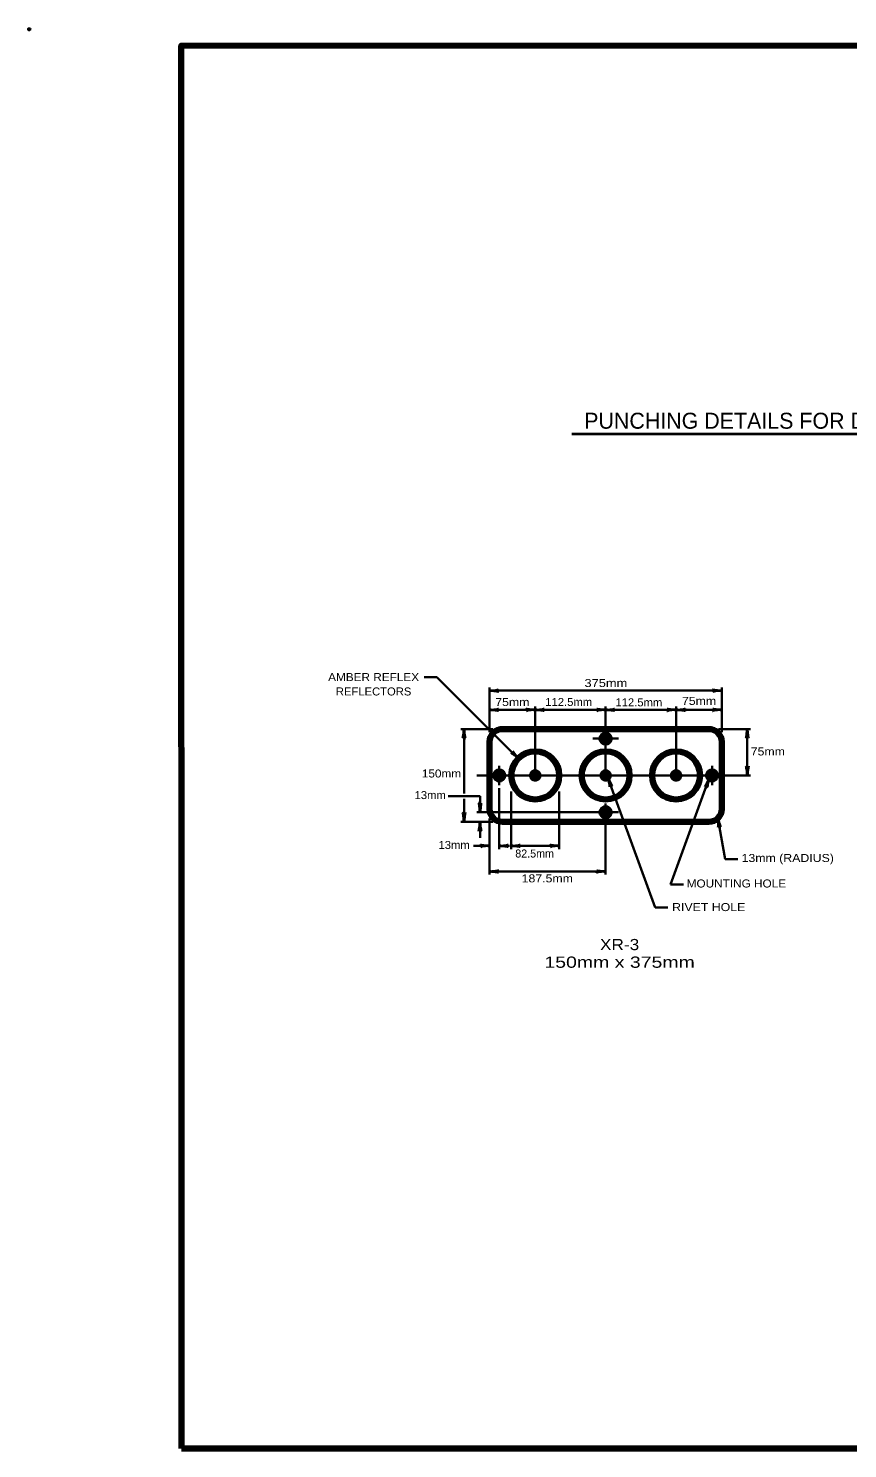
# Model space of a CAD drawing. Extents: x -74 to 639, y -412 to 42.
# Drawn here: x -74.5 to 181.5, y -402.1 to 41.7 of the extents above; entities that cross this region are included whole.
import ezdxf
from ezdxf.enums import TextEntityAlignment as Align

# ---------------------------------------------------------------- set-up
doc = ezdxf.new("R2010")
doc.units = 0
doc.header["$PDMODE"] = 32
doc.header["$PDSIZE"] = 0.5
doc.layers.add('1', color=7, linetype='Continuous', lineweight=40)

msp = doc.modelspace()

# ---------------------------------------------------------------- linework, layer by layer
at = {"layer": '1'}
msp.add_line((95.322, -84.95), (302.217, -84.95), dxfattribs=at)
at = {"layer": '1', "lineweight": 35}
for p, q in [((53.122, -160.979), (49.122, -160.979)), ((78.578, -186.434), (53.122, -160.979)), ((69.631, -178.238), (69.631, -164.238)), ((69.631, -165.238), (142.131, -165.238)), ((142.131, -178.238), (142.131, -164.238)), ((83.881, -171.238), (69.631, -171.238)), ((83.881, -191.738), (83.881, -170.238)), ((105.881, -191.738), (105.881, -170.238)), ((127.881, -191.738), (127.881, -170.238)), ((70.631, -177.238), (60.631, -177.238)), ((61.631, -197.404), (61.631, -177.238)), ((141.131, -177.238), (151.131, -177.238)), ((150.131, -191.738), (150.131, -177.238)), ((105.881, -180.238), (101.881, -180.238)), ((105.881, -180.238), (109.881, -180.238)), ((72.631, -191.738), (72.631, -188.738)), ((139.131, -191.738), (139.131, -188.738)), ((65.631, -191.738), (142.131, -191.738)), ((72.631, -191.738), (72.631, -194.738)), ((106.588, -192.445), (121.334, -232.957)), ((138.247, -192.622), (126.155, -225.845)), ((139.131, -191.738), (139.131, -194.738)), ((142.131, -191.738), (151.131, -191.738)), ((66.631, -198.238), (56.631, -198.238)), ((61.631, -206.238), (61.631, -199.071)), ((66.631, -198.238), (66.631, -203.238)), ((72.631, -195.738), (72.631, -214.738)), ((76.381, -196.738), (76.381, -214.738)), ((91.381, -196.738), (91.381, -214.738)), ((105.881, -203.238), (65.631, -203.238)), ((105.881, -222.738), (105.881, -200.488)), ((105.881, -203.238), (109.881, -203.238)), ((70.631, -206.238), (60.631, -206.238)), ((66.631, -206.238), (66.631, -211.238)), ((69.631, -222.738), (69.631, -205.238)), ((140.959, -205.066), (143.217, -217.869)), ((69.631, -213.738), (64.631, -213.738)), ((75.881, -213.738), (72.631, -213.738)), ((76.381, -213.738), (91.381, -213.738)), ((69.631, -221.738), (105.881, -221.738)), ((143.217, -217.869), (147.217, -217.869)), ((126.155, -225.845), (130.155, -225.845)), ((121.334, -232.957), (125.334, -232.957))]:
    msp.add_line(p, q, dxfattribs=at)
at = {"layer": '1', "lineweight": 90}
for p, q in [((73.631, -177.238), (138.131, -177.238)), ((69.631, -202.238), (69.631, -181.238)), ((142.131, -181.238), (142.131, -202.238)), ((138.131, -206.238), (73.631, -206.238))]:
    msp.add_line(p, q, dxfattribs=at)
at = {"layer": '1', "lineweight": 158}
msp.add_line((633.015, -402.068), (-26.651, -402.068), dxfattribs=at)
msp.add_lwpolyline([(633.015, 36.349), (-26.735, 36.265), (-26.651, -402.068)], dxfattribs=at)
at = {"layer": '1', "lineweight": 35}
msp.add_lwpolyline([(83.881, -171.238), (105.881, -171.238), (127.881, -171.238), (142.131, -171.238)], dxfattribs=at)
at = {"layer": '1', "lineweight": 90}
for centre, radius in [((105.881, -180.238), 1.25), ((83.881, -191.738), 7.5), ((105.881, -191.738), 7.5), ((127.881, -191.738), 7.5), ((72.631, -191.738), 1.25), ((83.881, -191.738), 1), ((105.881, -191.738), 1), ((127.881, -191.738), 1), ((139.131, -191.738), 1.25), ((105.881, -203.238), 1.25)]:
    msp.add_circle(centre, radius, dxfattribs=at)
for centre, start, end in [((73.631, -181.238), 90, 180), ((138.131, -181.238), 0, 90), ((73.631, -202.238), 180, 270), ((138.131, -202.238), 270, 0)]:
    msp.add_arc(centre, 4, start, end, dxfattribs=at)
at = {"layer": '1'}
for centre, major_axis, ratio, start_param, end_param in [((70.722, -164.961), (-1.786, -0.156), 0.122415, 0.8963533, 3.1415927), ((70.722, -164.961), (-1.786, -0.156), 0.122415, 0.8963533, 3.1415927), ((70.752, -165.449), (-1.756, 0.176), 0.07063, 3.1407148, 5.41811), ((70.752, -165.449), (-1.756, 0.176), 0.07063, 3.1407148, 5.41811), ((141.04, -165.514), (1.786, 0.156), 0.122415, 0.8963533, 3.1415927), ((141.04, -165.514), (1.786, 0.156), 0.122415, 0.8963533, 3.1415927), ((141.01, -165.026), (1.756, -0.176), 0.07063, 3.1407148, 5.41811), ((141.01, -165.026), (1.756, -0.176), 0.07063, 3.1407148, 5.41811), ((70.722, -170.961), (-1.786, -0.156), 0.122415, 0.8963533, 3.1415927), ((70.722, -170.961), (-1.786, -0.156), 0.122415, 0.8963533, 3.1415927), ((70.752, -171.449), (-1.756, 0.176), 0.07063, 3.1407148, 5.41811), ((70.752, -171.449), (-1.756, 0.176), 0.07063, 3.1407148, 5.41811), ((82.79, -171.514), (1.786, 0.156), 0.122415, 0.8963533, 3.1415927), ((82.79, -171.514), (1.786, 0.156), 0.122415, 0.8963533, 3.1415927), ((82.76, -171.026), (1.756, -0.176), 0.07063, 3.1407148, 5.41811), ((82.76, -171.026), (1.756, -0.176), 0.07063, 3.1407148, 5.41811), ((84.972, -170.961), (-1.786, -0.156), 0.122415, 0.8963533, 3.1415927), ((84.972, -170.961), (-1.786, -0.156), 0.122415, 0.8963533, 3.1415927), ((85.002, -171.449), (-1.756, 0.176), 0.07063, 3.1407148, 5.41811), ((85.002, -171.449), (-1.756, 0.176), 0.07063, 3.1407148, 5.41811), ((104.79, -171.514), (1.786, 0.156), 0.122415, 0.8963533, 3.1415927), ((104.79, -171.514), (1.786, 0.156), 0.122415, 0.8963533, 3.1415927), ((104.76, -171.026), (1.756, -0.176), 0.07063, 3.1407148, 5.41811), ((104.76, -171.026), (1.756, -0.176), 0.07063, 3.1407148, 5.41811), ((106.972, -170.961), (-1.786, -0.156), 0.122415, 0.8963533, 3.1415927), ((106.972, -170.961), (-1.786, -0.156), 0.122415, 0.8963533, 3.1415927), ((107.002, -171.449), (-1.756, 0.176), 0.07063, 3.1407148, 5.41811), ((107.002, -171.449), (-1.756, 0.176), 0.07063, 3.1407148, 5.41811), ((126.79, -171.514), (1.786, 0.156), 0.122415, 0.8963533, 3.1415927), ((126.79, -171.514), (1.786, 0.156), 0.122415, 0.8963533, 3.1415927), ((126.76, -171.026), (1.756, -0.176), 0.07063, 3.1407148, 5.41811), ((126.76, -171.026), (1.756, -0.176), 0.07063, 3.1407148, 5.41811), ((128.972, -170.961), (-1.786, -0.156), 0.122415, 0.8963533, 3.1415927), ((128.972, -170.961), (-1.786, -0.156), 0.122415, 0.8963533, 3.1415927), ((129.002, -171.449), (-1.756, 0.176), 0.07063, 3.1407148, 5.41811), ((129.002, -171.449), (-1.756, 0.176), 0.07063, 3.1407148, 5.41811), ((141.04, -171.514), (1.786, 0.156), 0.122415, 0.8963533, 3.1415927), ((141.04, -171.514), (1.786, 0.156), 0.122415, 0.8963533, 3.1415927), ((141.01, -171.026), (1.756, -0.176), 0.07063, 3.1407148, 5.41811), ((141.01, -171.026), (1.756, -0.176), 0.07063, 3.1407148, 5.41811), ((61.419, -178.358), (0.176, 1.756), 0.07063, 3.1407148, 5.41811), ((61.419, -178.358), (0.176, 1.756), 0.07063, 3.1407148, 5.41811), ((61.907, -178.329), (-0.156, 1.786), 0.122415, 0.8963533, 3.1415927), ((61.907, -178.329), (-0.156, 1.786), 0.122415, 0.8963533, 3.1415927), ((149.919, -178.358), (0.176, 1.756), 0.07063, 3.1407148, 5.41811), ((149.919, -178.358), (0.176, 1.756), 0.07063, 3.1407148, 5.41811), ((150.407, -178.329), (-0.156, 1.786), 0.122415, 0.8963533, 3.1415927), ((150.407, -178.329), (-0.156, 1.786), 0.122415, 0.8963533, 3.1415927), ((77.611, -185.858), (1.373, -1.152), 0.122415, 0.8963533, 3.1415927), ((77.611, -185.858), (1.373, -1.152), 0.122415, 0.8963533, 3.1415927), ((77.935, -185.492), (1.118, -1.366), 0.07063, 3.1407148, 5.41811), ((77.935, -185.492), (1.118, -1.366), 0.07063, 3.1407148, 5.41811), ((149.855, -190.647), (0.156, -1.786), 0.122415, 0.8963533, 3.1415927), ((149.855, -190.647), (0.156, -1.786), 0.122415, 0.8963533, 3.1415927), ((150.343, -190.617), (-0.176, -1.756), 0.07063, 3.1407148, 5.41811), ((150.343, -190.617), (-0.176, -1.756), 0.07063, 3.1407148, 5.41811), ((106.772, -193.57), (-0.436, 1.711), 0.07063, 3.1407148, 5.41811), ((106.772, -193.57), (-0.436, 1.711), 0.07063, 3.1407148, 5.41811), ((107.221, -193.376), (-0.757, 1.625), 0.122415, 0.8963533, 3.1415927), ((107.221, -193.376), (-0.757, 1.625), 0.122415, 0.8963533, 3.1415927), ((137.665, -193.602), (0.766, 1.59), 0.07063, 3.1407148, 5.41811), ((137.665, -193.602), (0.766, 1.59), 0.07063, 3.1407148, 5.41811), ((138.134, -193.742), (0.464, 1.731), 0.122415, 0.8963533, 3.1415927), ((138.134, -193.742), (0.464, 1.731), 0.122415, 0.8963533, 3.1415927), ((61.355, -205.147), (0.156, -1.786), 0.122415, 0.8963533, 3.1415927), ((61.355, -205.147), (0.156, -1.786), 0.122415, 0.8963533, 3.1415927), ((61.843, -205.117), (-0.176, -1.756), 0.07063, 3.1407148, 5.41811), ((61.843, -205.117), (-0.176, -1.756), 0.07063, 3.1407148, 5.41811), ((66.355, -202.147), (0.156, -1.786), 0.122415, 0.8963533, 3.1415927), ((66.355, -202.147), (0.156, -1.786), 0.122415, 0.8963533, 3.1415927), ((66.843, -202.117), (-0.176, -1.756), 0.07063, 3.1407148, 5.41811), ((66.843, -202.117), (-0.176, -1.756), 0.07063, 3.1407148, 5.41811), ((66.419, -207.358), (0.176, 1.756), 0.07063, 3.1407148, 5.41811), ((66.419, -207.358), (0.176, 1.756), 0.07063, 3.1407148, 5.41811), ((66.907, -207.329), (-0.156, 1.786), 0.122415, 0.8963533, 3.1415927), ((66.907, -207.329), (-0.156, 1.786), 0.122415, 0.8963533, 3.1415927), ((140.946, -206.206), (-0.132, 1.76), 0.07063, 3.1407148, 5.41811), ((141.421, -206.093), (-0.464, 1.731), 0.122415, 0.8963533, 3.1415927), ((68.54, -214.014), (1.786, 0.156), 0.122415, 0.8963533, 3.1415927), ((68.54, -214.014), (1.786, 0.156), 0.122415, 0.8963533, 3.1415927), ((68.51, -213.526), (1.756, -0.176), 0.07063, 3.1407148, 5.41811), ((68.51, -213.526), (1.756, -0.176), 0.07063, 3.1407148, 5.41811), ((73.722, -213.461), (-1.786, -0.156), 0.122415, 0.8963533, 3.1415927), ((73.722, -213.461), (-1.786, -0.156), 0.122415, 0.8963533, 3.1415927), ((73.752, -213.949), (-1.756, 0.176), 0.07063, 3.1407148, 5.41811), ((73.752, -213.949), (-1.756, 0.176), 0.07063, 3.1407148, 5.41811), ((77.472, -213.461), (-1.786, -0.156), 0.122415, 0.8963533, 3.1415927), ((77.472, -213.461), (-1.786, -0.156), 0.122415, 0.8963533, 3.1415927), ((77.502, -213.949), (-1.756, 0.176), 0.07063, 3.1407148, 5.41811), ((77.502, -213.949), (-1.756, 0.176), 0.07063, 3.1407148, 5.41811), ((90.29, -214.014), (1.786, 0.156), 0.122415, 0.8963533, 3.1415927), ((90.29, -214.014), (1.786, 0.156), 0.122415, 0.8963533, 3.1415927), ((90.26, -213.526), (1.756, -0.176), 0.07063, 3.1407148, 5.41811), ((90.26, -213.526), (1.756, -0.176), 0.07063, 3.1407148, 5.41811), ((70.722, -221.461), (-1.786, -0.156), 0.122415, 0.8963533, 3.1415927), ((70.722, -221.461), (-1.786, -0.156), 0.122415, 0.8963533, 3.1415927), ((70.752, -221.949), (-1.756, 0.176), 0.07063, 3.1407148, 5.41811), ((70.752, -221.949), (-1.756, 0.176), 0.07063, 3.1407148, 5.41811), ((104.79, -222.014), (1.786, 0.156), 0.122415, 0.8963533, 3.1415927), ((104.79, -222.014), (1.786, 0.156), 0.122415, 0.8963533, 3.1415927), ((104.76, -221.526), (1.756, -0.176), 0.07063, 3.1407148, 5.41811), ((104.76, -221.526), (1.756, -0.176), 0.07063, 3.1407148, 5.41811)]:
    msp.add_ellipse(centre, major_axis=major_axis, ratio=ratio, start_param=start_param, end_param=end_param, dxfattribs=at)
msp.add_point((-74.235, 41.432), dxfattribs=at)

# ---------------------------------------------------------------- texts
for s, height, p in [('PUNCHING DETAILS FOR DELINEATOR MOUNTING PLAQUES', 5, (197.989, -83.404)), ('PUNCHING DETAILS FOR DELINEATOR MOUNTING PLAQUES', 5, (197.989, -83.404)), ('82.5mm', 2.5, (83.679, -217.377))]:
    msp.add_text(s, height=height, dxfattribs=at).set_placement(p, align=Align.CENTER)
for s, height, width, p in [('AMBER REFLEX', 2.5, 1.1, (33.377, -162.248)), ('375mm', 2.5, 1.2, (105.951, -164.111)), ('REFLECTORS', 2.5, 1.05, (33.377, -166.748)), ('75mm', 2.5, 1.15, (76.719, -170.053)), ('112.5mm', 2.5, 1.05, (94.336, -170.029)), ('112.5mm', 2.5, 1.05, (116.252, -170.149)), ('75mm', 2.5, 1.15, (135.057, -169.707)), ('75mm', 2.5, 1.15, (156.552, -185.488)), ('150mm', 2.5, 1.1, (54.579, -192.373)), ('13mm', 2.5, 1.05, (51.05, -199.119)), ('13mm', 2.5, 1.05, (58.532, -214.709)), ('13mm (RADIUS)', 2.5, 1.15, (162.775, -218.774)), ('187.5mm', 2.5, 1.15, (87.637, -225.153)), ('MOUNTING HOLE', 2.5, 1.1, (146.726, -226.747)), ('RIVET HOLE', 2.5, 1.15, (138.083, -234.118)), ('XR-3', 3.5, 1.15, (110.233, -246.327)), ('150mm x 375mm', 3.5, 1.3, (110.233, -251.827))]:
    msp.add_text(s, height=height, dxfattribs=dict(at, width=width)).set_placement(p, align=Align.CENTER)

doc.saveas('drawing.dxf')
